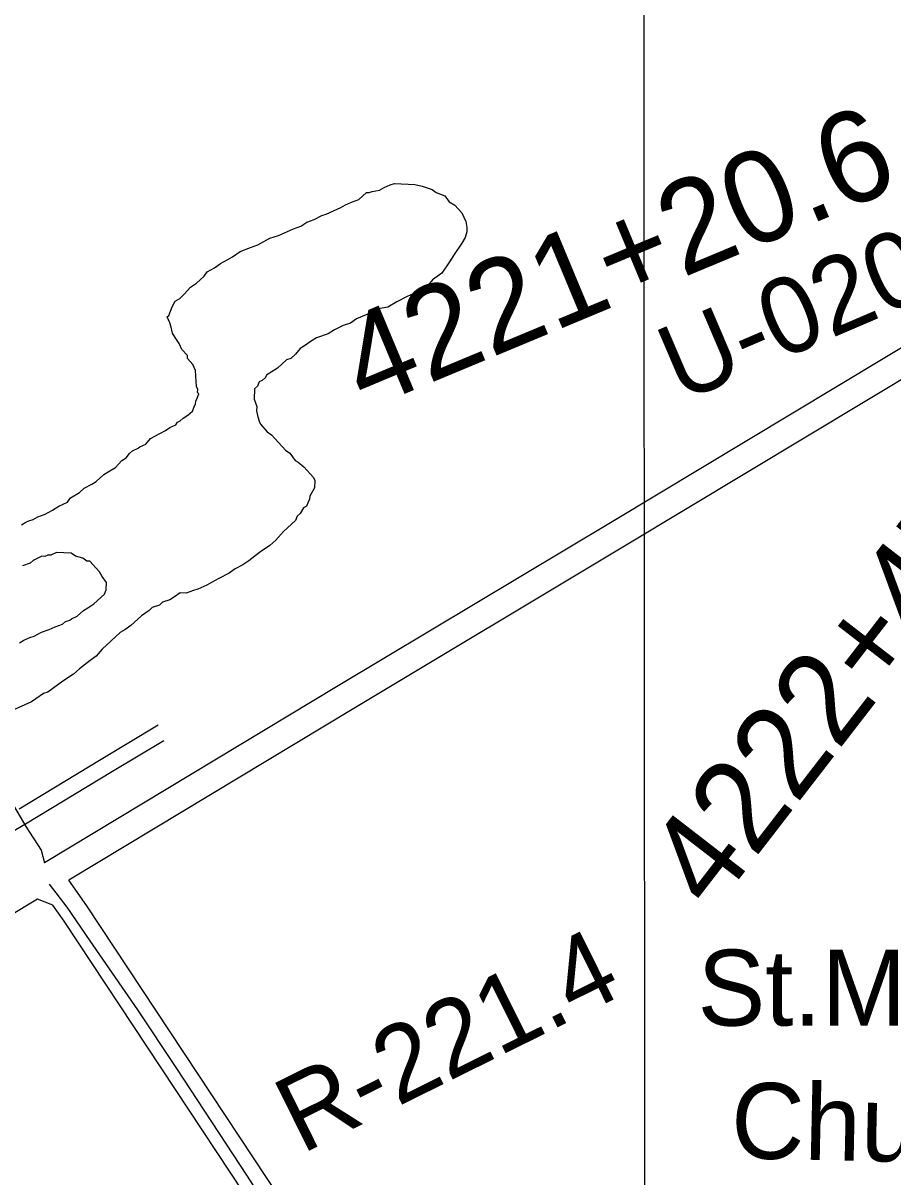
# Model space of a CAD drawing. Extents: x 3297753 to 3335611, y 652252 to 677623.
# Drawn here: x 3306440 to 3307391, y 670404 to 671666 of the extents above; entities that cross this region are included whole.
import ezdxf

# ---------------------------------------------------------------- set-up
doc = ezdxf.new("R2010")
doc.units = 0
for name, color, linetype in [('V-DTCH-CNTR', 7, 'Continuous'), ('V-GRID-MAJR', 7, 'Continuous'), ('V-RAIL-TRAK', 7, 'Continuous'), ('V-RIVR-RANG-IDEN', 7, 'Continuous'), ('V-ROAD-CNTR', 7, 'Continuous'), ('V-SITE-OTLN-IDEN', 7, 'Continuous'), ('V-SITE-VEGE', 7, 'Continuous'), ('V-SURV-IDEN', 7, 'Continuous')]:
    doc.layers.add(name, color=color, linetype=linetype)

msp = doc.modelspace()

# ---------------------------------------------------------------- linework, layer by layer
at = {"layer": 'V-DTCH-CNTR'}
msp.add_lwpolyline([(3307138.1, 669673.7), (3307076.9, 669777.6), (3307024, 669870.4), (3306961.2, 669970), (3306936.7, 670016.1), (3306883.6, 670103), (3306820.3, 670203.1), (3306751.1, 670302.4), (3306685.5, 670405), (3306607.8, 670523.8), (3306565.9, 670586.8), (3306513.8, 670662.4), (3306488.5, 670699.2), (3306469.1, 670724.3)], dxfattribs=at)
at = {"layer": 'V-GRID-MAJR'}
msp.add_spline([(3307129.4, 657636), (3307127.2, 660664.7), (3307122.8, 666726.2), (3307118.4, 672787.6), (3307116.2, 675820.3)], degree=3, dxfattribs=at)
at = {"layer": 'V-RAIL-TRAK'}
for points in [[(3306435.9, 670806.7), (3306525.8, 670860.7), (3306588.1, 670898.2)], [(3305959.1, 670502.2), (3306074.6, 670570.8), (3306191.5, 670639.7), (3306332.7, 670725.7), (3306443.1, 670790.1), (3306538.1, 670847.7), (3306594.3, 670881.1)]]:
    msp.add_lwpolyline(points, dxfattribs=at)
at = {"layer": 'V-ROAD-CNTR'}
for points in [[(3305845.3, 671679.2), (3306003, 671437.3), (3306148.8, 671232.6), (3306276.4, 671046.1), (3306385.3, 670883.5), (3306405.3, 670851.4), (3306423.5, 670820.6), (3306443.2, 670787.2), (3306460.1, 670761.2), (3306463.7, 670747.6)], [(3307585.3, 671418.7), (3307580.9, 671416.3), (3307477.5, 671356.7), (3307084.4, 671120.4), (3306784.8, 670941.1)], [(3307599.6, 671392.4), (3307595.6, 671390.2), (3307492.7, 671330.8), (3307099.8, 671094.7), (3306800.2, 670915.3)], [(3306784.7, 670941), (3306463.7, 670747.6)], [(3306800.2, 670915.3), (3306490.2, 670728.6)], [(3307129.4, 669735.3), (3307046.2, 669876.5), (3306962.2, 670008.2), (3306890, 670126.3), (3306864.7, 670162.9), (3306833.2, 670215.1), (3306722.2, 670379.7), (3306510.1, 670700.6), (3306490.2, 670728.6)], [(3306455.9, 670707.9), (3305695.7, 670249.9)], [(3307103.5, 669720.1), (3307020.6, 669860.8), (3306936.8, 669992.3), (3306864.8, 670109.9), (3306839.5, 670146.6), (3306807.9, 670198.9), (3306697.2, 670363), (3306485.3, 670683.6), (3306472.7, 670701.4), (3306455.9, 670707.9)]]:
    msp.add_lwpolyline(points, dxfattribs=at)
at = {"layer": 'V-SITE-VEGE'}
for points in [[(3306627.2, 671246), (3306628.9, 671249.2), (3306629.1, 671252.3), (3306630.8, 671255.5), (3306632.6, 671260.2), (3306631.1, 671261.8), (3306631.2, 671265), (3306629.8, 671268.3), (3306628.9, 671285.8), (3306626, 671292.3), (3306619.9, 671298.9), (3306620, 671302.1), (3306613.9, 671308.8), (3306611, 671315.3), (3306606.5, 671321.8), (3306603.6, 671326.7), (3306602.2, 671333.2), (3306600.8, 671338), (3306597.9, 671344.5), (3306599.6, 671346), (3306603.2, 671355.4), (3306606.6, 671361.7), (3306611.5, 671364.6), (3306616.5, 671369.2), (3306623.2, 671376.9), (3306629.8, 671381.4), (3306638.1, 671389), (3306641.4, 671393.7), (3306649.6, 671398.1), (3306656.2, 671402.6), (3306664.3, 671407), (3306669.2, 671410), (3306677.5, 671416), (3306688.8, 671420.3), (3306696.9, 671423.2), (3306709.9, 671430.6), (3306719.6, 671433.4), (3306735.9, 671440.6), (3306744, 671443.5), (3306750.5, 671448), (3306758.6, 671450.8), (3306766.8, 671455.3), (3306771.6, 671456.7), (3306787.8, 671463.9), (3306792.8, 671466.9), (3306799.2, 671469.8), (3306807.3, 671472.7), (3306815.6, 671480.3), (3306818.8, 671480.2), (3306822.1, 671481.6), (3306830.1, 671482.9), (3306835, 671485.8), (3306841.5, 671488.8), (3306846.3, 671490.1), (3306868.6, 671489.2), (3306876.5, 671487.3), (3306887.5, 671483.6), (3306892.1, 671480.2), (3306901.5, 671476.7), (3306906, 671470.1), (3306912.3, 671466.6), (3306919.9, 671458.3), (3306924.2, 671448.6), (3306925.6, 671442.2), (3306925.4, 671437.4), (3306923.5, 671431.1), (3306920.1, 671424.9), (3306911.6, 671412.5), (3306906.5, 671404.7), (3306898, 671392.3), (3306888.1, 671384.8), (3306883, 671378.6), (3306870, 671371.2), (3306860.2, 671366.8), (3306848.8, 671361), (3306839, 671355), (3306824.6, 671352.4), (3306818, 671347.9), (3306805, 671342.1), (3306798.4, 671337.6), (3306790.3, 671334.8), (3306780.6, 671330.4), (3306774, 671325.9), (3306761.1, 671321.6), (3306756.2, 671318.7), (3306748, 671312.6), (3306743.1, 671309.7), (3306738, 671303.5), (3306733, 671298.9), (3306728.2, 671297.5), (3306718.3, 671288.4), (3306711.7, 671283.9), (3306706.8, 671280.9), (3306705.1, 671277.8), (3306701.7, 671274.8), (3306698.5, 671273.3), (3306696.7, 671268.6), (3306693.4, 671265.6), (3306692.9, 671254.4), (3306695.8, 671246.3), (3306695.6, 671241.6)], [(3306438.5, 671117), (3306443.4, 671120), (3306446.6, 671121.4), (3306451.5, 671122.8), (3306456.4, 671125.8), (3306464.5, 671128.6), (3306472.6, 671133.1), (3306479.2, 671137.6), (3306489, 671141.9), (3306492.3, 671146.6), (3306502.1, 671152.5), (3306507.1, 671157.1), (3306515.3, 671161.6), (3306520.2, 671164.5), (3306528.5, 671172.1), (3306533.4, 671175.1), (3306541.5, 671179.6), (3306548.2, 671187.2), (3306553.1, 671190.2), (3306556.5, 671194.9), (3306559.8, 671197.9), (3306566.3, 671200.8), (3306568, 671202.3), (3306574.5, 671205.3), (3306579.5, 671211.4), (3306595.9, 671220.3), (3306600.8, 671223.3), (3306607.3, 671226.2), (3306609, 671229.3), (3306612.2, 671230.7), (3306615.5, 671233.8), (3306620.5, 671236.8), (3306625.4, 671241.3), (3306627.2, 671246)], [(3306695.6, 671241.6), (3306696.9, 671235.1), (3306698.3, 671230.3), (3306699.7, 671227), (3306707.3, 671218.7), (3306712, 671215.4), (3306727.2, 671198.8), (3306731.8, 671195.4), (3306737.9, 671187.2)], [(3306737.9, 671187.2), (3306741, 671185.5), (3306747.1, 671180.4), (3306757.8, 671168.8), (3306759.3, 671165.6), (3306758.9, 671157.6), (3306753.8, 671148.3), (3306753.6, 671145.1), (3306751.9, 671142), (3306750.1, 671137.3), (3306746.9, 671135.8), (3306743.4, 671129.6), (3306740.1, 671126.5), (3306738.3, 671121.8), (3306725, 671109.6), (3306716.7, 671100.4), (3306710, 671094.3), (3306698.6, 671086.9), (3306687, 671077.8), (3306680.5, 671073.3), (3306672.3, 671068.8), (3306665.7, 671064.3), (3306654.3, 671058.4), (3306646.2, 671054), (3306641.3, 671051), (3306631.5, 671046.7), (3306626.7, 671045.3), (3306618.6, 671042.4), (3306612.2, 671042.7), (3306605.7, 671038.2), (3306600.8, 671035.2), (3306592.7, 671032.4), (3306589.4, 671029.3), (3306581.3, 671026.5), (3306578, 671023.4), (3306569.7, 671017.4), (3306558.1, 671006.8), (3306551.6, 671002.2), (3306546.6, 670999.3), (3306526.8, 670981), (3306520.1, 670973.3), (3306513.5, 670968.8), (3306501.9, 670959.7), (3306495.3, 670953.6), (3306483.8, 670946.2), (3306467.4, 670934.1), (3306462.6, 670932.7), (3306454.3, 670926.7), (3306449.4, 670923.7), (3306416.9, 670909.1)], [(3306436.2, 670988), (3306441.1, 670991), (3306447.6, 670993.9), (3306452.5, 670995.3), (3306460.6, 670999.7), (3306468.7, 671002.6), (3306475.2, 671005.5), (3306483.3, 671008.3), (3306486.6, 671011.4), (3306491.4, 671012.8), (3306493.1, 671014.3), (3306499.6, 671017.2), (3306506.2, 671023.3), (3306511.1, 671026.3), (3306517.7, 671030.8), (3306529.3, 671041.4), (3306531.1, 671046.1), (3306531.4, 671054.1), (3306526.9, 671060.7), (3306524, 671065.6), (3306513.3, 671077.2), (3306510.1, 671077.3), (3306505.5, 671080.7), (3306497.6, 671082.6)], [(3306497.6, 671082.6), (3306493, 671086), (3306477, 671086.7), (3306470.5, 671083.8), (3306467.4, 671083.9), (3306464.1, 671082.4), (3306460.9, 671082.6), (3306451.2, 671078.2), (3306447.9, 671075.2), (3306439.8, 671072.3)]]:
    msp.add_lwpolyline(points, dxfattribs=at)

# ---------------------------------------------------------------- texts
at = {"layer": 'V-RIVR-RANG-IDEN'}
for s, rotation, p in [('U-020', 23.158, (3307159.1, 671250.4)), ('R-221.4', 26.4083, (3306744.8, 670428.6))]:
    msp.add_text(s, height=83, rotation=rotation, dxfattribs=at).set_placement(p)
at = {"layer": 'V-SITE-OTLN-IDEN'}
msp.add_text("St.Mary's", height=83, dxfattribs=at).set_placement((3307177.7, 670569.5))
msp.add_text('Church', height=83, rotation=358.7818, dxfattribs=at).set_placement((3307213.7, 670424.7))
at = {"layer": 'V-SURV-IDEN'}
for s, rotation, p in [('4221+20.6', 22.6436, (3306814.5, 671242.3)), ('4222+47.7', 52.2886, (3307194.6, 670692.8))]:
    msp.add_text(s, height=100, rotation=rotation, dxfattribs=at).set_placement(p)

doc.saveas('drawing.dxf')
